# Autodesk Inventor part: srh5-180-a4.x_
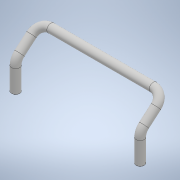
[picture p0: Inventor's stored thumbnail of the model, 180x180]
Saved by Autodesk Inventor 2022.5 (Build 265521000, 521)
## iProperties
Created: 2018-05
Part Number: srh5-180-a4.x_
Material: 一般
Document SubType Name: Modeling
Designer: imaocorp
Density: 1 g/cm^3
Appearance: 既定
Sending System: SOLIDWORKS 2016-2016286
MC: AMD64
MC_MODEL: AMD64 Family 21 Model 2 Stepping 0, AuthenticAMD
OS: Windows_NT
FRU: Parasolid Version 28.0, build 224,  7-29-2016
FORMAT: text
GUISE: transmit
KEY: srh5-180-a4
FILE: srh5-180-a4.x_t
DATE: Thu May 10 13:59:37 2018
Author: imaocorp
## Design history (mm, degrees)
feature "Base1"
node "ソリッド1"
